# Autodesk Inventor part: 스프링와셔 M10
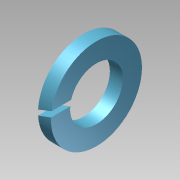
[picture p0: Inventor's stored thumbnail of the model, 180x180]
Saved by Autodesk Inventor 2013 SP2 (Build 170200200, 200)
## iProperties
Created: 2025-04
Part Number: 스프링와셔 M10
Material: Generic
Document SubType Name: Modeling
Designer: i
Density: 1 g/cm^3
변환 표준: STEP AP214IS
전처리기: Build: 200, Release: 2013 SP2 Update 6 - Date: Thu 07/17/2014
전송 단위: 밀리미터
불확실성: 0.01
Author: i
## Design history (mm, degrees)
node "스프링와셔 M101"
body "Solid1"
node "기준1"
